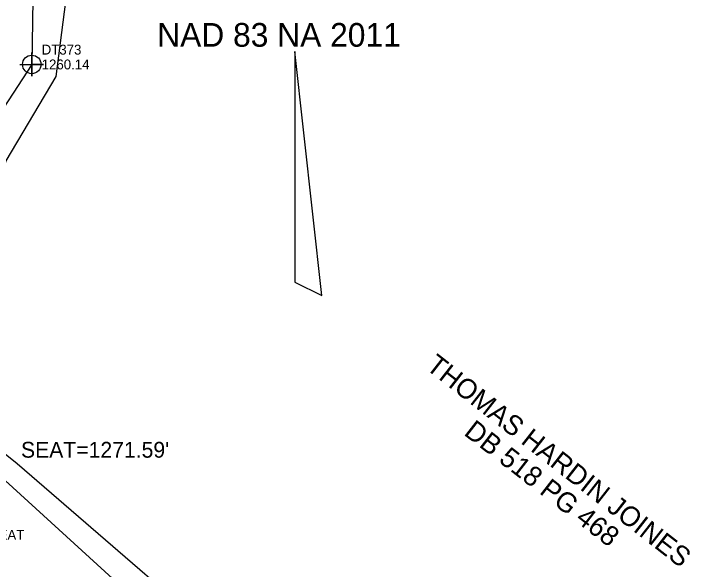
# Model space of a CAD drawing. Extents: x 1390773 to 1392296, y 959928 to 960736.
# Drawn here: x 1391644.1 to 1391817.8, y 960338.9 to 960479.4 of the extents above; entities that cross this region are included whole.
import ezdxf

# ---------------------------------------------------------------- set-up
doc = ezdxf.new("R2010")
doc.units = 0
for name, color, linetype in [('CTL North Arrow NAD 83 NA 2011 CELL', 7, 'Continuous'), ('Exist Hydro Jurisdictional Stream or Body of Water', 7, 'Continuous'), ('Exist Hydro Stream or Body of Water Cogo Elevation', 7, 'Continuous'), ('Exist Hydro Stream or Body of Water Cogo Number', 7, 'Continuous'), ('Exist Hydro Stream or Body of Water Cogo Point CELL', 7, 'Continuous'), ('Exist Property Line', 7, 'Continuous'), ('Exist Property Owner Text', 7, 'Continuous'), ('Exist Right of Way Line', 7, 'Continuous'), ('Exist Structure Major Bridge Seat Top Elevation', 7, 'Continuous'), ('Exist Utilities Sanitary Sewer Manhole Cogo Comment', 7, 'Continuous'), ('Exist Vegetation Woods Line', 7, 'Continuous')]:
    doc.layers.add(name, color=color, linetype=linetype)

msp = doc.modelspace()

# ---------------------------------------------------------------- linework, layer by layer
at = {"layer": 'CTL North Arrow NAD 83 NA 2011 CELL'}
msp.add_lwpolyline([(1391715.09, 960411.5), (1391721.96, 960408.09), (1391715.09, 960469.82)], close=True, dxfattribs=at)
at = {"layer": 'Exist Hydro Jurisdictional Stream or Body of Water'}
msp.add_lwpolyline([(1391649.06, 960494.04), (1391648.63, 960466.55), (1391627.2, 960433.7), (1391623.14, 960411.17), (1391625.85, 960360.36), (1391624.5, 960352.95)], dxfattribs=at)
at = {"layer": 'Exist Hydro Stream or Body of Water Cogo Point CELL'}
msp.add_lwpolyline([(1391645.63, 960466.55), (1391651.63, 960466.55), (1391648.63, 960466.55), (1391648.63, 960463.55), (1391648.63, 960469.55)], dxfattribs=at)
msp.add_circle((1391648.63, 960466.55), 2.34, dxfattribs=at)
at = {"layer": 'Exist Right of Way Line'}
msp.add_line((1391357.82, 960620.3), (1391697.89, 960310.24), dxfattribs=at)
at = {"layer": 'Exist Vegetation Woods Line'}
msp.add_lwpolyline([(1391924, 960170.47), (1391835.6, 960211.5), (1391761.23, 960261.63), (1391710.07, 960309.24), (1391644.93, 960365.54), (1391630.28, 960377.24), (1391631.75, 960409.9), (1391642.16, 960442.2), (1391654.83, 960463.47), (1391658.63, 960493.66)], dxfattribs=at)

# ---------------------------------------------------------------- texts
at = {"layer": 'CTL North Arrow NAD 83 NA 2011 CELL'}
msp.add_text('NAD 83 NA 2011', height=6, dxfattribs=at).set_placement((1391680.32, 960471.03))
at = {"layer": 'Exist Hydro Stream or Body of Water Cogo Elevation'}
msp.add_text('1260.14', height=2.5, dxfattribs=at).set_placement((1391651.13, 960465.3))
at = {"layer": 'Exist Hydro Stream or Body of Water Cogo Number'}
msp.add_text('DT373', height=2.5, dxfattribs=at).set_placement((1391651.13, 960469.05))
at = {"layer": 'Exist Property Line'}
msp.add_text('THOMAS HARDIN JOINES', height=5, rotation=321.9874, dxfattribs=at).set_placement((1391747.96, 960389.68))
at = {"layer": 'Exist Property Owner Text'}
msp.add_text('DB 518 PG 468', height=5, rotation=322.1878, dxfattribs=at).set_placement((1391757.57, 960373.04))
at = {"layer": 'Exist Structure Major Bridge Seat Top Elevation'}
msp.add_text("SEAT=1271.59'", height=4, dxfattribs=at).set_placement((1391645.9, 960367.12))
at = {"layer": 'Exist Utilities Sanitary Sewer Manhole Cogo Comment'}
msp.add_text('3543 SEAT', height=2.5, dxfattribs=at).set_placement((1391629.65, 960346.35))

doc.saveas('drawing.dxf')
